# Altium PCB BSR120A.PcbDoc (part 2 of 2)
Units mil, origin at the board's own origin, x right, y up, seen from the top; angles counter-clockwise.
Board outline 3250 x 2500 mil, 4 copper layers (Top Layer, MidLayer1, MidLayer2, Bottom Layer), stack 61.2 mil thick; 56 components, 15 nets, 102 pads, 73 vias.
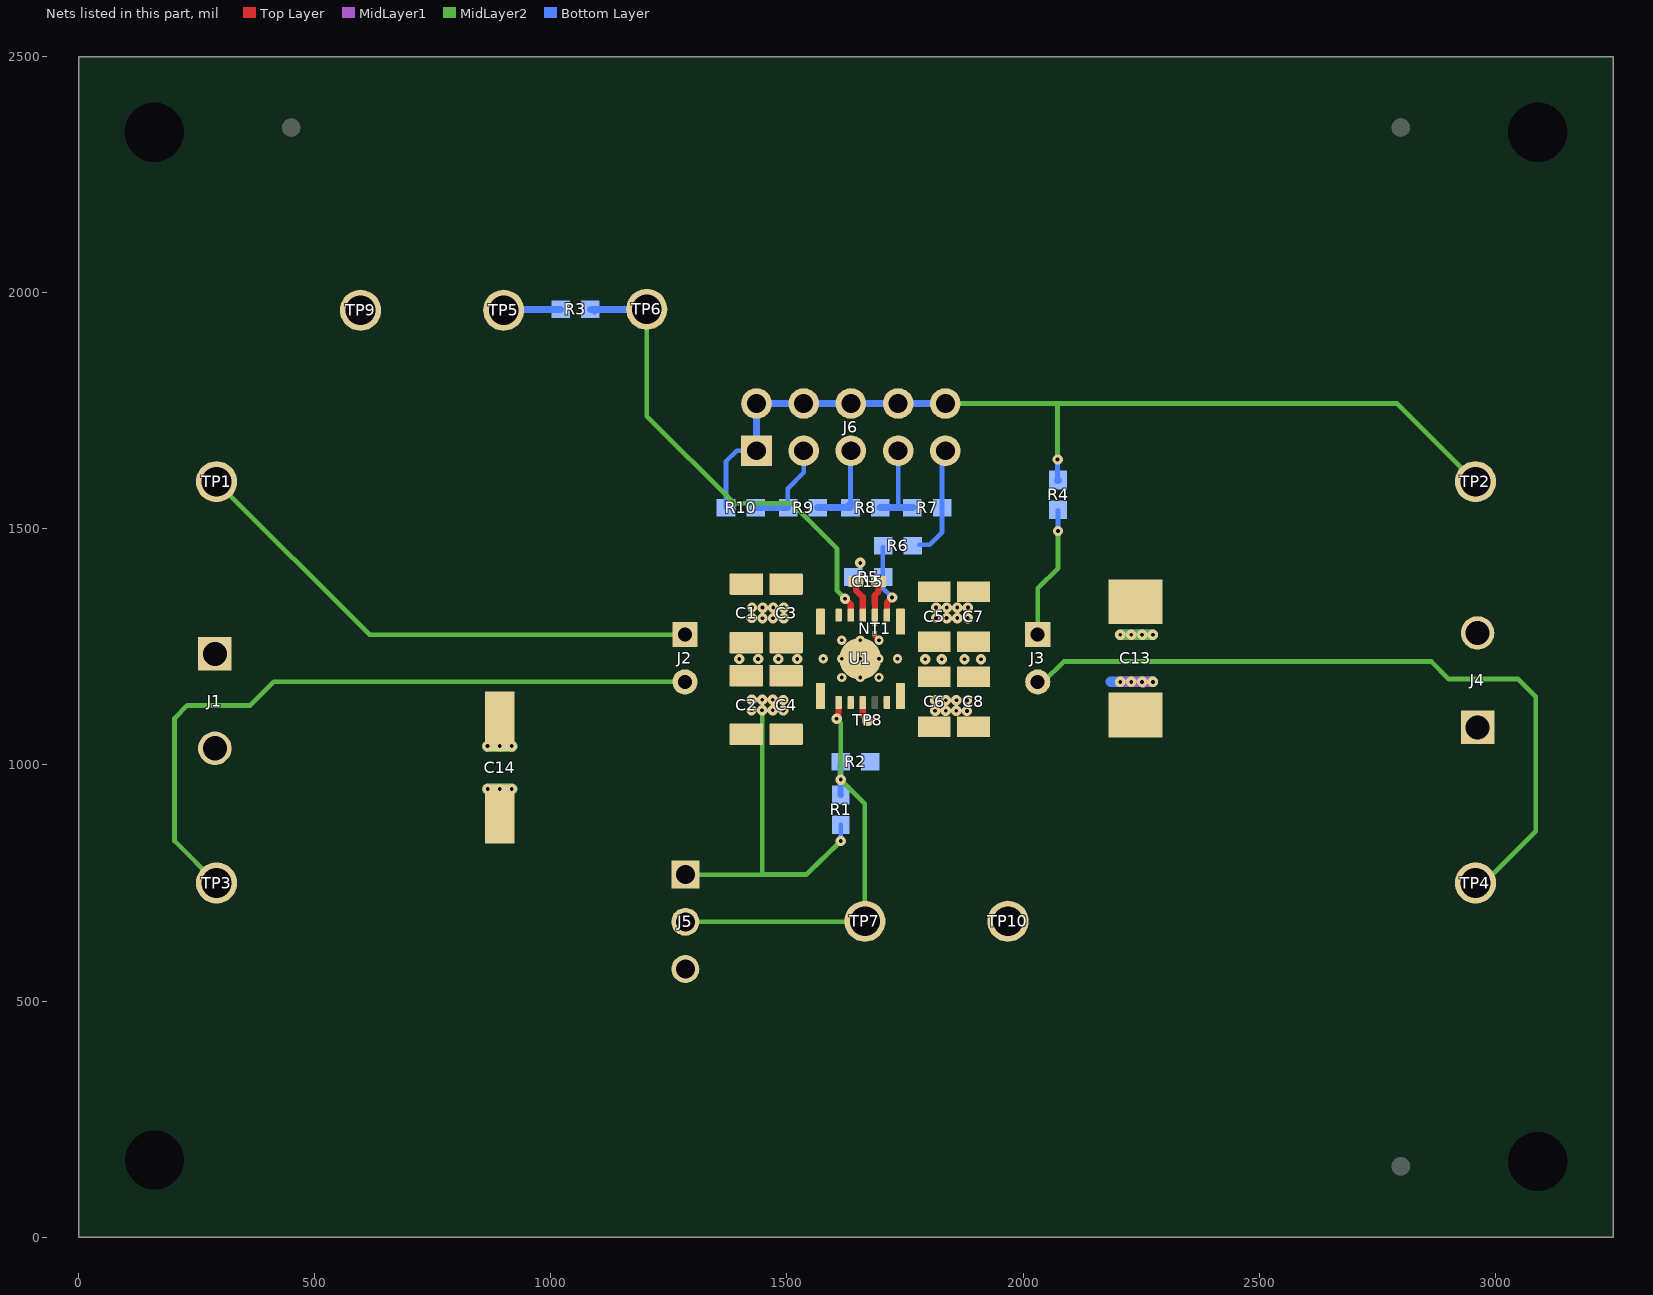
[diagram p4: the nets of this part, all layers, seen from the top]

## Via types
v1: diameter 22, hole 8, Top Layer to Bottom Layer, 62 vias
v2: diameter 19.68, hole 7.87, Top Layer to Bottom Layer, 11 vias

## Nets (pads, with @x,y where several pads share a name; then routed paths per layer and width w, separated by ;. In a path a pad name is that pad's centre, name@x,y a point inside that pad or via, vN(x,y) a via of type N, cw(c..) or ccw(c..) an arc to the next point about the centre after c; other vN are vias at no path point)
2.5: J6.9 R6.2 R7.1 | length 234.8
  Bottom Layer w10: R6.2@1780.25,1466.25 1801.88,1466.25 1828.5,1492.87 R7.1@1828.5,1545 1828.5,1658.6 J6.9@1835.4,1665.5
3.3: J6.7 R7.2 R8.1 | length 188.9
  Bottom Layer w10: 1735.4,1545.6 J6.7@1735.4,1665.5
  Bottom Layer w15: R8.1@1697.5,1545 R7.2@1766.5,1545
5.0: J6.5 R8.2 R9.1 | length 213.9
  Bottom Layer w10: R8.2@1634.5,1545 J6.5@1634.5,1664.6
  Bottom Layer w15: R9.1@1564.5,1545 R8.2@1634.5,1545 ; J6.5@1634.5,1664.6 J6.5@1635.4,1665.5 ; R8.2@1635.4,1554.9 R8.2@1634.5,1554.01 ; R8.2@1634.5,1545 R8.2@1634.5,1554.01 ; R8.2@1634.5,1545 1630,1549.5 R8.2@1634.5,1554.01
12: J6.3 R9.2 R10.1 | length 202.3
  Bottom Layer w10: R9.2@1501.5,1545 1501.5,1585.5 1535.4,1619.4 J6.3@1535.4,1665.5
  Bottom Layer w15: R10.1@1433.7,1545 R9.2@1501.5,1545
15: J6.1 J6.2 J6.4 J6.6 J6.8 J6.10 R4.2 R10.2 TP2.1 | length 2047.6
  MidLayer2 w10: J6.10@1835.4,1765.5 2792.5,1765.5 2958.74,1599.26 TP2.1@2975.26,1599.26 ; v1(2073.1,1646.9) 2073.1,1765.4 ; TP2.1@2957.26,1599.26 TP2.1@2958,1600
  Bottom Layer w10: R10.2@1370.7,1545 1370.7,1642.7 1393.5,1665.5 J6.1@1435.4,1665.5 ; R4.2@2073.1,1602.6 v1(2073.1,1646.9)
  Bottom Layer w15: J6.1@1435.4,1665.5 J6.2@1435.4,1765.5 J6.4@1535.4,1765.5 J6.6@1635.4,1765.5 J6.8@1735.4,1765.5 J6.10@1835.4,1765.5 ; R4.2@2074,1603.5 2073.1,1602.6 R4.2@2075,1602.6
AGND: C15.2 NT1.1 R5.1 U1.10 | length 74.3
  Top Layer w13: U1.10@1686.16,1317.26 1686.02,1359.02 1693.54,1366.54 C15.2@1693.54,1388.48
  other v1: 1655,1428
EN: J5.2 R1.1 R2.2 TP7.1 U1.2 | length 933.5
  Top Layer w13: v1@1609.39,1101.02 U1.2@1609.39,1132.22
  MidLayer2 w10: J5.2@1284.74,667.8 1663.8,667.8 TP7.1@1665,669 1665,918 v1(1614,969) 1614,1089 v1(1605,1098)
  Bottom Layer w13: R2.2@1613.5,1004 1613.5,936.99 R1.1@1614,936.5
FB: R5.2 R6.1 U1.9 | length 157.3
  Top Layer w13: U1.9@1711.75,1317.26 1711.75,1343.84 v1(1722.65,1354.74)
  Bottom Layer w10: R6.1@1703.5,1461 1703.1,1461.41 1703.1,1374.29 v1(1722.65,1354.74)
NetC15_1: C15.1 U1.11 | length 76.8
  Top Layer w13: C15.1@1646,1388 1646,1370 1660.57,1355.43 U1.11@1660.57,1317.26
NetTP8_1: TP8.1 U1.4 | length 41.5
  Top Layer w13: U1.4@1660.57,1132.22 1660.57,1105.43 TP8.1@1671,1095
PG_PU: R3.1 TP5.1 | length 119.5
  Bottom Layer w15: TP5.1@901,1965 R3.1@1020.5,1965
PGND: C1.1 C2.1 C3.1 C4.1 C5.1 C6.1 C7.1 C8.1 C13.2 C14.2 J1.2 J2.2 J3.2 J4.1 J5.3 NT1.2 R2.1 TP3.1 TP4.1 TP9.1 TP10.1 U1.3 U1.6 U1.13 U1.15 | length 3384.7
  Top Layer w10: 1686,1272.93 NT1.2@1686,1279
  MidLayer1 w22: v1(2206,1176) v1(2275,1176) ; v1@2252.6,1176 2253.08,1175.52 v1@2253.56,1176
  MidLayer2 w10: TP3.1@292,750 203,839 203,1099 230,1126 363,1126 413,1176 J2.2@1284,1176 ; J3.2@2018,1163 J3.2@2024,1169 ; J3.2@2018,1175 J3.2@2024,1169 ; J3.2@2043.82,1162 2031,1162 J3.2@2024,1169 ; TP4.1@2934,750 TP4.1@2958,750 ; TP4.1@2976,750 3086,860 3086,1145 3049,1182 2902,1182 2865,1219 2086,1219 2043,1176 J3.2@2031,1176 J3.2@2024,1169
  MidLayer2 w24: v1(866.18,949.18) v1(917.18,949.2)
  Bottom Layer w22: 2185.56,1176 v1(2229,1176) 2252.6,1176 2253.08,1175.52 2253.56,1176 v1(2275,1176)
  Bottom Layer w24: v1(866.18,949.18) v1(917.18,949.2)
  other v1: 891.68,949.19 2252,1176 1398.92,1224.48 1438.92,1224.48 1481.92,1224.48 1521.92,1224.48 1793,1224 1828,1224 1876,1224 1911,1224
  other v2: 1616.08,1185.37 1655.45,1185.37 1694.82,1185.37 1576.71,1224.74 1616.08,1224.74 1655.45,1224.74 1694.82,1224.74 1734.19,1224.74 1616.08,1264.11 1655.45,1264.11 1694.82,1264.11
PGOOD: R3.2 TP6.1 U1.12 | length 1021.9
  Top Layer w13: v1(1623,1352) 1634.98,1340.02 U1.12@1634.98,1317.26
  MidLayer2 w10: TP6.1@1203,1965 1203,1739 1388,1554 1510,1554 1606,1458 1606,1369 v1(1623,1352)
  Bottom Layer w15: R3.2@1083.5,1965 R3.2@1095,1965 ; R3.2@1092,1962 R3.2@1095,1965 ; TP6.1@1203,1965 R3.2@1095,1965
VIN: C1.2 C2.2 C3.2 C4.2 C14.1 J1.1 J2.1 J5.1 R1.2 TP1.1 U1.1 U1.14 | length 1967.9
  MidLayer2 w10: TP1.1@292.74,1599.26 616,1276 J2.1@1284,1276 ; J5.1@1284.74,767.8 1447,767.93 ; v1(1447.35,1115.7) 1447.35,768.27 1447,767.93 ; v1@1492.56,1135.83 v1@1492.73,1136 ; v1(1614,839) 1541,768 1447,767.93
  MidLayer2 w24: v1(866.02,1040) v1(917.02,1040.02)
  Bottom Layer w10: v1(1614,839) R1.2@1614,873.5
  Bottom Layer w24: v1(866.02,1040) v1(917.02,1040.02)
  other v1: 891.52,1040.01 1492.21,1115.4 1424.91,1115.7 1469.78,1115.7 1425.13,1138 1447.57,1138 1470,1138 1492.43,1137.7 1425.65,1311.25 1448.08,1310.95 1470.51,1310.95 1492.94,1310.95 1448.3,1333.25 1470.73,1333.25 1493.17,1333.25 1425.87,1333.55
VOUT: C5.2 C6.2 C7.2 C8.2 C13.1 J3.1 J4.2 R4.1 U1.7 U1.8 | length 419.3
  MidLayer2 w10: J3.1@2031,1276 2031,1374 2074,1417 v1(2074,1495.5)
  MidLayer2 w22: v1(2206,1276) v1(2275,1276)
  Bottom Layer w10: v1(2074,1495.5) R4.1@2074,1539.5
  Bottom Layer w22: v1(2206,1276) v1(2275,1276)
  other v1: 1881.08,1114.4 1813.78,1114.7 1836.21,1114.7 1858.64,1114.7 1814,1137 1836.43,1137 1858.87,1137 1881.3,1136.7 2229,1276 2252,1276 1815.57,1311.3 1838,1311 1860.43,1311 1882.87,1311 1838.22,1333.3 1860.65,1333.3 1883.09,1333.3 1815.79,1333.6
pads on no net: FID1.1 FID2.1 FID3.1 FID4.1 FID5.1 FID6.1 SH-J5.0 SH-J6.0 U1.5

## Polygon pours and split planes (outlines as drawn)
PGND on Top Layer "PGND" (solid, pour order 348): 3251.65,2496.39 3251.67,-3.61 1.65,-3.61 1.65,2496.39
VIN on Top Layer "VIN_L01_P342" (solid, remove dead copper, pour order 342): 1372,1407 1372,1295 1541,1295 1561,1275 1581,1275 1582,1276 1582,1330 1536,1376 1536,1407
VIN on Top Layer "VIN_L01_P341" (solid, remove dead copper, pour order 341): 1372,1150 1537,1150 1561,1174 1581,1174 1581,1087 1534,1040 1372,1040
VOUT on Top Layer "VOUT_L01_P340" (solid, remove dead copper, pour order 340): 1948.2,1391 1948.2,1296 1771,1296 1751,1276 1731,1276 1730,1277 1730,1341 1780,1391
VOUT on Top Layer "VOUT_L01_P338" (solid, remove dead copper, pour order 338): 1938,1149 1775,1149 1750,1174 1730,1174 1730,1089.08 1763.08,1056 1938,1056
AGND on Top Layer "AGND_L01_P343" (solid, remove dead copper, pour order 343): 1643,1438 1643,1302.29 1709.18,1302.29 1709.95,1301.52 1711.57,1303.13 1711.56,1434.91 1700.94,1445.53 ccw(c1678.11,-22492.67) 1650.52,1445.53
VIN on MidLayer1 "Top-Vin" (solid, remove dead copper, pour order 350): 738.6,1015 1534,1015 1534,1152 1362,1152 1362,1298 1534,1298 1534,1468 212,1468 212,1136 617.6,1136
VOUT on MidLayer1 "Top-Vout" (solid, remove dead copper, pour order 352): 2527.44,1014 1785,1014 1785,1153 1946,1153 1946,1298 1785,1298 1785,1471.5 3046,1471.5 3046,1193.48 2706.92,1193.48
PGND on MidLayer1 "Layer_2-PGND" (solid, remove dead copper, pour order 354): 0,-0.01 3250,0 3250,2500 0,2500
PGND on Bottom Layer "Layer_2-PGND" (solid, remove dead copper, pour order 362): 0,-0.01 3250,0 3250,2500 0,2500
PGND on MidLayer2 "PGND" (solid, pour order 360): 3250,0 0,0.15 0,2500 3250,2500

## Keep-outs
Keep-Out Layer:
  lines w10: 0,-6 0,2496 3250,2496 3250,-6 0,-6
  text ".Layer_Name" at 72.5,-1858.99 h60

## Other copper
Top Layer:
  region net VOUT: 2306.06,1395.48 2172.92,1395.48 2172.92,1261.34 2306.06,1261.34
  rectangle net VIN: 855,1028 929,1158
  region net PGND: 928.2,961.2 854.2,961.2 854.2,831.2 928.2,831.2
  rectangle net PGND: 2169.94,1056.52 2303.08,1190.66
  pour cut-out: 158.66,322.51 166.66,322.51 cw(c166.66,167.51) 321.66,167.51 321.66,158.51 cw(c165.66,158.51) 165.66,2.51 156.66,2.51 cw(c156.66,157.51) 1.66,157.51 1.66,165.51 cw(c158.66,165.51)
  pour cut-out: 2930.49,157.66 2930.49,165.66 cw(c3085.49,165.66) 3085.49,320.66 3094.49,320.66 cw(c3094.49,164.66) 3250.49,164.66 3250.49,155.66 cw(c3095.49,155.66) 3095.49,0.66 3087.49,0.66 cw(c3087.49,157.66)
  pour cut-out: 3092.34,2180.49 3084.34,2180.49 cw(c3084.34,2335.49) 2929.34,2335.49 2929.34,2344.49 cw(c3085.34,2344.49) 3085.34,2500.49 3094.34,2500.49 cw(c3094.34,2345.49) 3249.34,2345.49 3249.34,2337.49 cw(c3092.34,2337.49)
  pour cut-out: 319.51,2342.34 319.51,2334.34 cw(c164.51,2334.34) 164.51,2179.34 155.51,2179.34 cw(c155.51,2335.34) -0.49,2335.34 -0.49,2344.34 cw(c154.51,2344.34) 154.51,2499.34 162.51,2499.34 cw(c162.51,2342.34)
  pour cut-out: 1631.92,1401 1662,1401 1662,1375.48 1631.92,1375.48
  text ".Layer_Name" at -6.24,-1858.99 h60
MidLayer1:
  pour cut-out: 61,166 61,161 ccw(c159,161) 159,63 164,63 ccw(c164,160) 261,160 261,166 ccw(c164,166) 164,263 158,263 ccw(c158,166)
  pour cut-out: 61,166 61,161 ccw(c159,161) 159,63 164,63 ccw(c164,160) 261,160 261,166 ccw(c164,166) 164,263 158,263 ccw(c158,166)
  pour cut-out: 3087,60 3092,60 ccw(c3092,158) 3190,158 3190,163 ccw(c3093,163) 3093,260 3087,260 ccw(c3087,163) 2990,163 2990,157 ccw(c3087,157)
  pour cut-out: 3087,60 3092,60 ccw(c3092,158) 3190,158 3190,163 ccw(c3093,163) 3093,260 3087,260 ccw(c3087,163) 2990,163 2990,157 ccw(c3087,157)
  pour cut-out: 3190,2337 3190,2342 ccw(c3092,2342) 3092,2440 3087,2440 ccw(c3087,2343) 2990,2343 2990,2337 ccw(c3087,2337) 3087,2240 3093,2240 ccw(c3093,2337)
  pour cut-out: 3190,2337 3190,2342 ccw(c3092,2342) 3092,2440 3087,2440 ccw(c3087,2343) 2990,2343 2990,2337 ccw(c3087,2337) 3087,2240 3093,2240 ccw(c3093,2337)
  pour cut-out: 163,2440 158,2440 ccw(c158,2342) 60,2342 60,2337 ccw(c157,2337) 157,2240 163,2240 ccw(c163,2337) 260,2337 260,2343 ccw(c163,2343)
  pour cut-out: 163,2440 158,2440 ccw(c158,2342) 60,2342 60,2337 ccw(c157,2337) 157,2240 163,2240 ccw(c163,2337) 260,2337 260,2343 ccw(c163,2343)
  text ".Layer_Name" at -6.24,-1858.99 h60
MidLayer2:
  pour cut-out: 61,166 61,161 ccw(c159,161) 159,63 164,63 ccw(c164,160) 261,160 261,166 ccw(c164,166) 164,263 158,263 ccw(c158,166)
  pour cut-out: 3087,60 3092,60 ccw(c3092,158) 3190,158 3190,163 ccw(c3093,163) 3093,260 3087,260 ccw(c3087,163) 2990,163 2990,157 ccw(c3087,157)
  pour cut-out: 3190,2337 3190,2342 ccw(c3092,2342) 3092,2440 3087,2440 ccw(c3087,2343) 2990,2343 2990,2337 ccw(c3087,2337) 3087,2240 3093,2240 ccw(c3093,2337)
  pour cut-out: 163,2440 158,2440 ccw(c158,2342) 60,2342 60,2337 ccw(c157,2337) 157,2240 163,2240 ccw(c163,2337) 260,2337 260,2343 ccw(c163,2343)
  pour cut-out: 1284,1136.78 cw(c1284,1176) 1244.78,1176 cw(c1284,1176) 1284,1215.22 cw(c1284,1176) 1323.22,1176 cw(c1284,1176)
  pour cut-out: 2031,1136.78 cw(c2031,1176) 1991.78,1176 cw(c2031,1176) 2031,1215.22 cw(c2031,1176) 2070.22,1176 cw(c2031,1176)
  text ".Layer_Name" at -6.24,-1858.99 h60
Bottom Layer:
  rectangle net AGND: 1620,1373 1666,1439
  pour cut-out: 158.66,322.51 166.66,322.51 cw(c166.66,167.51) 321.66,167.51 321.66,158.51 cw(c165.66,158.51) 165.66,2.51 156.66,2.51 cw(c156.66,157.51) 1.66,157.51 1.66,165.51 cw(c158.66,165.51)
  pour cut-out: 2930.49,157.66 2930.49,165.66 cw(c3085.49,165.66) 3085.49,320.66 3094.49,320.66 cw(c3094.49,164.66) 3250.49,164.66 3250.49,155.66 cw(c3095.49,155.66) 3095.49,0.66 3087.49,0.66 cw(c3087.49,157.66)
  pour cut-out: 3092.34,2180.49 3084.34,2180.49 cw(c3084.34,2335.49) 2929.34,2335.49 2929.34,2344.49 cw(c3085.34,2344.49) 3085.34,2500.49 3094.34,2500.49 cw(c3094.34,2345.49) 3249.34,2345.49 3249.34,2337.49 cw(c3092.34,2337.49)
  pour cut-out: 319.51,2342.34 319.51,2334.34 cw(c164.51,2334.34) 164.51,2179.34 155.51,2179.34 cw(c155.51,2335.34) -0.49,2335.34 -0.49,2344.34 cw(c154.51,2344.34) 154.51,2499.34 162.51,2499.34 cw(c162.51,2342.34)
  text ".Layer_Name" at 72.5,-1858.99 h60

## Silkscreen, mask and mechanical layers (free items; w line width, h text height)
Top Overlay:
  circle w10: c1570.92,1096.48 r10
  circle w10: c1569.51,1096.48 r1.41
  lines w6: 1346.25,526.12 1355.25,526.12 1404.25,526.12 1404.25,545 ; 1346.25,807.12 1355.25,807.12 1404.25,807.12 1404.25,791 ; 1348.25,670.12 1404.25,670.12 1405.25,669.12 ; 1405.25,653 1405.25,669.12 ; 1405.25,690 1405.25,669.12
  text "'.PRJ_Title'" at 1169,2279 h120
  text "PG_PU" at 792,2067 h50
  text "PGOOD" at 1094,2067 h50
  text "PGND" at 505,2066 h50
  text "3.3V" at 1759,1841 h50 r90
  text "2.5V" at 1859,1841 h50 r90
  text "15V" at 1459,1840 h50 r90
  text "12V" at 1558,1838 h50 r90
  text "5.0V" at 1658,1836 h50 r90
  text "VIN" at 242,1767 h50
  text "VOUT" at 2874,1763 h50
  text "S+" at 250,1696 h50
  text "S+" at 2919.75,1695.26 h50
  text "VOUT  / SELECT" at 1936,1656 h50
  text "VOUT" at 3007.5,1426 h50
  text "VIN" at 67,1424 h50
  text "+" at 2210,1416 h70
  text "+" at 378,1406 h70
  text "Vout" at 1863,1345 h50
  text "Vin" at 1207,1327 h50
  text "+" at 2098,1298 h45
  text "+" at 1172,1280.01 h45
  text "+" at 756,1144 h50
  text "PGND" at 50,848 h50
  text "PGND" at 3002,848 h50
  text "ON" at 1364,716 h50
  text "VIN" at 242,606 h50
  text "VOUT" at 2874.25,603.74 h50
  text "OFF" at 1357.25,571.12 h50
  text "S-" at 254,538 h50
  text "S-" at 2920,536 h50
  text "EN" at 1629,524 h50
  text "PGND" at 1876,524 h50
  text "ENABLE" at 1170,429 h50
  text "'.PRJ_Number'.PCB_Rev" at 2403,63 h45
  text ".Layer_Name" at 72.5,-1858.99 h60
Bottom Overlay:
  text ".Layer_Name" at 72.5,-1858.99 h60
Top Paste:
  text ".Layer_Name" at 72.5,-1858.99 h60
Bottom Paste:
  text ".Layer_Name" at 72.5,-1858.99 h60
Top Solder:
  text ".Layer_Name" at 72.5,-1858.99 h60
  text ".Layer_Name" at 72.5,-1858.99 h60
Bottom Solder:
  text ".Layer_Name" at 72.5,-1858.99 h60
Drill Guide:
  text ".Layer_Name" at 72.5,-1858.99 h60
M1 Board Outline:
  the board outline again, w4
  text ".Layer_Name" at -6.24,-1858.99 h60
M2 Board Dimensions:
  rectangle: -379.5,-1400.5 -4.5,-1275.5
  rectangle: -504.5,-1275.5 -379.5,-1150.5
  lines w7: -504.5,-1275.5 495.5,-1275.5 ; -379.5,-1400.5 -379.5,-1150.5 ; -254.5,-1400.5 -254.5,-1150.5 ; -4.5,-1400.5 -4.5,-1150.5 ; 245.5,-1400.5 245.5,-1150.5 ; -504.5,-1400.5 -504.5,-1150.5 495.5,-1150.5 495.5,-1400.5 -504.5,-1400.5
  text ".Layer_Name" at -6.24,-1858.99 h60
M3 3D STEP Top:
  text ".Layer_Name" at -6.24,-1858.99 h60
M4 3D STEP Bottom:
  text ".Layer_Name" at -6.24,-1858.99 h60
M5 Assembly Top:
  lines w10: -816.18,-1930.67 5033.85,-1930.67 ; -816.18,-1727.33 5033.85,-1727.33 ; -816.18,-1524 -816.18,-2134 3188.81,-2134 ; 759.82,-2134 -815.68,-2134 -815.68,-1524 5033.85,-1524 5033.85,-2134 2712.44,-2134 ; 1467.71,-2134 1467.71,-1524 ; 2498.49,-1727.33 2498.49,-1524 ; 3220.38,-1727.33 3220.38,-1524 ; 3724.27,-2140.5 3724.27,-1937.67
  text "COMPONENTS MARKED 'DNP' SHOULD NOT BE POPULATED." at 526.95,-1319 h60
  text "ASSEMBLY VARIANT:" at 526.45,-1434.5 h60
  text ".VariantName" at 1554.58,-1434.5 h60
  text "PCB VIEWED FROM TOP SIDE" at -772.37,-1656.17 h60
  text "BOARD #:" at 1511.22,-1656.17 h60
  text ".PRJ_Number" at 1970.1,-1656.17 h60
  text "REV:" at 2657.12,-1656.17 h60
  text ".PCB_Rev" at 2889.57,-1656.17 h60
  text "SVN REV:" at 3290.4,-1656.17 h60
  text ".VersionControl_RevNumber" at 3784.59,-1656.17 h60
  text "TID #:" at 1511.22,-1859.5 h60
  text ".TID" at 1970.1,-1859.5 h60
  text "PLOT NAME =" at -772.37,-2064.84 h60
  text ".plot_File_Name" at -6.24,-2064.84 h60
  text "GENERATED    :" at 1513.22,-2064.84 h60
  text ".Print_Date" at 2237.05,-2064.84 h60
  text ".Print_Time" at 2828.25,-2064.84 h60
  text "TEXAS INSTRUMENTS" at 3895.9,-2064.84 h60
M6 Assembly Bottom:
  lines w10: -816.68,-1727.83 5033.85,-1727.83 ; -814.68,-1931.17 5033.85,-1931.17 ; 508.64,-2141 508.64,-1938.17 ; 1051.9,-1727.83 1051.9,-1524.5 ; 1540.16,-2134.5 5033.85,-2134.5 3575.46,-2134.5 ; 1780.32,-2134.5 -816.68,-2134.5 -816.68,-1524.5 5033.85,-1524.5 ; 1793.47,-1727.83 1793.47,-1524.5 ; 2824.25,-2134.5 2824.25,-1524.5 ; 5032.85,-2134.5 5032.85,-1524.5 ; 5033.35,-2134.5 5033.35,-1524.5
  text "COMPONENTS MARKED 'DNP' SHOULD NOT BE POPULATED." at 5199.86,-1318.5 h60
  text ".VariantName" at 3860.59,-1434.5 h60
  text "ASSEMBLY VARIANT:" at 4860.22,-1434.5 h60
  text ".VersionControl_RevNumber" at 531,-1656.67 h60
  text "SVN REV:" at 1017.32,-1656.67 h60
  text ".PCB_Rev" at 1422.08,-1656.67 h60
  text "REV:" at 1662.4,-1656.67 h60
  text "BOARD #:" at 2729.57,-1656.67 h60
  text "PCB VIEWED FROM BOTTOM SIDE" at 4989.53,-1656.67 h60
  text ".PRJ_Number" at 2311,-1661 h60
  text ".TID" at 2282.49,-1860 h60
  text "TID #:" at 2729.57,-1860 h60
  text "TEXAS INSTRUMENTS" at 340.95,-2065.34 h60
  text ".Print_Time" at 1522.77,-2065.34 h60
  text ".Print_Date" at 2141.53,-2065.34 h60
  text "GENERATED    :" at 2924.42,-2065.34 h60
  text ".plot_File_Name" at 4321.83,-2065.34 h60
  text "PLOT NAME =" at 4989.53,-2065.34 h60
M9 Title Sheet:
  drawing of 52 lines, arcs and shapes, not listed
  text "1" at 411,4431 h70
  text "2" at 3271,4431 h70
  text "3" at 6151,4431 h70
  text "4" at 9021,4431 h70
  text "A" at -941,3525 h70
  text "A" at 10359,3525 h70
  text "B" at -941,1633 h70
  text "B" at 10359,1633 h70
  text "C" at -941,-277 h70
  text "C" at 10359,-277 h70
  text "PROJECT TITLE:" at 7319,-1423 h45
  text ".PRJ_Title" at 7369,-1556.33 h60
  text "DESIGNED FOR:" at 7319,-1724 h45
  text ".PRJ_Customer" at 7369,-1864 h70
  text "FILE NAME:" at 7319,-2024 h45
  text ".PCB_File_Name_No_Path" at 7369,-2144 h70
  text "D" at -941,-2167 h70
  text "D" at 10359,-2167 h70
  text "Texas Instruments (TI) and/or its licensors do not warrant the accuracy or completeness of this specification" at 710.5,-2313.84 h60
  text "ENGINEER:" at 7319,-2314 h45
  text "LAYOUT BY:" at 8824,-2314 h45
  text "or any information contained therein. TI and/or its licensors do not warrant that this design will meet" at 665.51,-2426.5 h60
  text ".PRJ_Engineer" at 7369,-2468.99 h70
  text ".PCB_Layout" at 8874.5,-2468.99 h70
  text "the specifications, will be suitable for your application or fit for any particular purpose, or will operate in" at 665.51,-2539.17 h60
  text "ALTIUM DESIGNER VERSION:" at 8824,-2624 h45
  text "an implementation. TI and/or its licensors do not warrant that the design is production worthy. You should" at 665.51,-2651.83 h60
  text ".print_Scale" at 7369,-2757.33 h70
  text ".Application_BuildNumber" at 8874.5,-2757.33 h70
  text "completely validate and test your design implementation to confirm the system functionality for your application." at 710.5,-2764.5 h60
  text "1" at 411,-2969 h70
  text "2" at 3271,-2969 h70
  text "3" at 6151,-2969 h70
  text "4" at 9021,-2969 h70
M10 Fab Notes:
  drawing of 192 lines, arcs and shapes, not listed
  text "DESIGN INFORMATION" at 8358.52,4155.17 h60
  text "MIN. TRACK WIDTH:" at 7713.96,4023.05 h60
  text "mil" at 8965.46,4023.05 h60
  text "10" at 8744,4018.24 h60
  text "MIN. CLEARANCE:" at 7713.96,3898.92 h60
  text "mil" at 8965.46,3898.92 h60
  text "8" at 8744,3895.11 h60
  text "MIN. VIA PAD SIZE:" at 7713.96,3774.8 h60
  text "mil" at 8965.46,3774.8 h60
  text "22" at 8744,3770 h60
  text "0.05mm (2MIL)" at 8408.96,3644.9 h60
  text "MINIMUM ANNULAR RING" at 7384.73,3636.67 h60
  text "EXTERNAL" at 9116.96,3636.67 h60
  text "PER" at 7584.73,3526.55 h60
  text "IPC-D-275 CLASS 2 LEVEL C" at 7804.73,3526.54 h60
  text "MIL, HOLES" at 9292.96,3426.07 h60
  text "+/-" at 8900.5,3417.48 h60
  text "+/-" at 9754.5,3417.48 h60
  text "REGISTRATION TOLERANCES:" at 7384.73,3416.42 h60
  text "METAL" at 8584.5,3416.42 h60
  text "5" at 9160.7,3416.42 h60
  text "3" at 9993.7,3416.42 h60
  text "MIL" at 10109.96,3416.42 h60
  text "HOLE SIZE TOLERANCE (UNLESS OTHERWISE SPECIFIED):" at 7384.73,3318.1 h60
  text "+/-" at 9754.5,3315.23 h60
  text "3" at 9993.7,3314.17 h60
  text "MIL" at 10109.96,3314.17 h60
  text "MATERIAL:" at 7309.96,3176.52 h60
  text "FR-4 High Tg" at 8296.4,3048 h60
  text "X" at 8151.96,3040.01 h60
  text "FR-408" at 7730.96,3035.49 h60
  text "OTHER" at 9218.96,3035.49 h60
  text "62 MIL (1.6mm) +/-10%" at 8051.06,2892.46 h60
  text "X" at 7930.96,2890.01 h60
  text "THICKNESS:" at 7384.73,2884.24 h60
  text "OTHER" at 9335.96,2884.24 h60
  text "TOLERANCE:" at 7384.73,2745.92 h60
  text "X" at 8232.96,2745.92 h60
  text "ANSI IPC-6012 TYPE 3 CLASS 2" at 8410.98,2745.92 h60
  text "OTHER +/-" at 8410.96,2601.73 h60
  text "BOW & TWIST:" at 7384.73,2456.54 h60
  text "X" at 8232.96,2456.54 h60
  text "ANSI IPC-6012 TYPE 3 CLASS 2" at 8410.98,2456.54 h60
  text "OTHER +/-" at 8410.96,2309.85 h60
  text "DRILLING:" at 7309.96,2179.23 h60
  text "NC_DRILL FILES" at 9070.96,2074.04 h60
  text "REFERENCE:" at 7384.73,2070.1 h60
  text "X" at 8041.96,2070.01 h60
  text "AS SHOWN" at 8219.96,2070.1 h60
  text "X" at 8942.96,2070.1 h60
  text "OTHER" at 9368.96,1927.85 h60
  text "PTH COPPER THICKNESS:" at 7384.41,1924.32 h60
  text "X" at 8523.64,1924.32 h60
  text "20-30 um" at 8651.64,1924.32 h60
  text "BOARD FINISH:" at 7309.96,1776.73 h60
  text "SILKSCREEN:" at 7465.18,1666.6 h60
  text "X" at 8422.96,1666.6 h60
  text "TOP" at 8539.96,1666.6 h60
  text "X" at 8932.96,1666.6 h60
  text "BOTTOM" at 9050.96,1666.6 h60
  text "SILKSCREEN COLOR:" at 7465.18,1511.41 h60
  text "X" at 8421.96,1511.41 h60
  text "WHITE" at 8539.96,1511.41 h60
  text "OTHER" at 9050.96,1511.41 h60
  text "X" at 8552.96,1367.96 h60
  text "GREEN" at 8670.96,1367.96 h60
  text "OTHER" at 9288.96,1367.96 h60
  text "SOLDER RESIST COLOR:" at 7465.18,1361.1 h60
  text "MATTE" at 8670.96,1213.71 h60
  text "SEMI-GLOSS" at 9288.5,1213.07 h60
  text "X" at 9147,1205 h60
  text "IMMERSION GOLD (ENIG)" at 8370.96,1040.94 h60
  text "ENEPIG" at 9708.5,1033.72 h60
  text "SURFACE FINISH:" at 7309.96,1032.72 h60
  text "X" at 8192.96,1032.72 h60
  text "IMM. TIN/SILVER OR EQUIV" at 7639.5,895.4 h60
  text "OTHER" at 9070.96,891.47 h60
  text "ARRAY/PANEL:" at 7309.96,736.09 h60
  text "CUT AND TRIM PER M1 BOARD OUTLINE" at 8370.96,727.87 h60
  text "N.C. ROUTE" at 8370.96,591.9 h60
  text "X" at 9058.96,591.9 h60
  text "V. SCORE" at 9236.96,591.9 h60
  text "CERTIFICATION:" at 7309.96,462.77 h60
  text "MATERIALS AND WORKMANSHIP FOR ALL PCBS" at 8034.96,462.77 h60
  text "TO MEET OR EXCEED THE REQUIREMENTS OF:" at 8034.96,368.71 h60
  text "X" at 7672.47,240.08 h60
  text "ANSI IPC-A-600F CLASS ->" at 7800.46,240.08 h60
  text "X" at 9448.47,240.08 h60
  text "2" at 9558.46,240.08 h60
  text "1" at 9243.46,238.58 h60
  text "3" at 9912.46,238.58 h60
  text "X" at 8484.47,92.39 h60
  text "RoHS" at 8612.46,92.39 h60
  text "OTHER" at 9256.86,92.39 h60
  text "PER ORDER" at 9653.92,92.39 h60
  text "ALL BOARDS MUST MEET OR EXCEED UL94-V0 REQUIREMENTS." at 7337.5,-61.43 h60
  text "PCB MUST BEAR THE UL94V-0 UL REGISTERED MATERIAL ID NUMBER" at 7337.5,-177.5 h60
  text "ADDITIONAL REQUIREMENTS:" at 7309.96,-346.92 h60
  text "MICROSECTION:" at 7384.73,-454.05 h60
  text "YES" at 8290.46,-454.05 h60
  text "REQUIRED" at 9151.96,-598.38 h60
  text "BARE BOARD ELEC. TEST:" at 7384.73,-601.24 h60
  text "NONE" at 8690.46,-601.24 h60
  text "X" at 9033.96,-601.24 h60
  text "PER ORDER" at 9743.96,-601.24 h60
  text "X" at 7378.96,-753.24 h60
  text "7.87 MIL VIAS REQUIRE NON-CONDUCTIVE FILL AND PLANARIZE" at 7440,-807 h59
  text "XX MIL VIAS REQUIRE CONDUCTIVE FILL AND PLANARIZE" at 7501.88,-910.16 h60
  text "OUTER XX MIL TRACES REQUIRE 50 OHM SINGLE-ENDED IMPEDANCE" at 7500.89,-1073.54 h58
  text "LAYER 2 & 3 (INNER LAYERS) XX MIL WIDE, XX MIL SPACE / TRACES REQUIRE 100 OHM DIFFERENTIAL IMPEDANCE" at 7492.89,-1309.26 h60
  text ".Layer_Name" at -6.24,-1858.99 h60
M11 Gerber Information:
  lines w10: -816.18,-1930.67 5033.85,-1930.67 ; -816.18,-1727.33 5033.85,-1727.33 ; -816.18,-1524 -816.18,-2134 3188.81,-2134 ; 759.82,-2134 -815.68,-2134 -815.68,-1524 5033.85,-1524 5033.85,-2134 2712.44,-2134 ; 1467.71,-2134 1467.71,-1524 ; 2498.49,-1727.33 2498.49,-1524 ; 3220.38,-1727.33 3220.38,-1524 ; 3724.27,-2140.5 3724.27,-1937.67
  text "ALL ARTWORK VIEWED FROM TOP SIDE" at -772.37,-1656.17 h60
  text "BOARD #:" at 1511.22,-1656.17 h60
  text ".PRJ_Number" at 1970.1,-1656.17 h60
  text "REV:" at 2657.12,-1656.17 h60
  text ".PCB_Rev" at 2889.57,-1656.17 h60
  text "SVN REV:" at 3290.4,-1656.17 h60
  text ".VersionControl_RevNumber" at 3784.59,-1656.17 h60
  text "LAYER NAME =" at -772.37,-1858.99 h60
  text "TID #:" at 1511.22,-1859.5 h60
  text ".TID" at 1970.1,-1859.5 h60
  text "PLOT NAME =" at -772.37,-2064.84 h60
  text ".plot_File_Name" at -6.24,-2064.84 h60
  text "GENERATED    :" at 1513.22,-2064.84 h60
  text ".Print_Date" at 2237.05,-2064.84 h60
  text ".Print_Time" at 2828.25,-2064.84 h60
  text "TEXAS INSTRUMENTS" at 3895.9,-2064.84 h60
M12 Stackup:
  drawing of 251 lines, arcs and shapes, not listed
  text "Layer" at 4163.48,4087 h50
  text "Name" at 4449.01,4087 h50
  text "Material" at 5081.62,4087 h50
  text "Thickness" at 5669.94,4087 h50
  text "Constant" at 6093.54,4087 h50
  text "Board Layer Stack" at 6499.53,4087 h50
  text "1" at 4163.48,3987 h50
  text "Top Overlay" at 4449.01,3987 h50
  text "2" at 4163.48,3887 h50
  text "Top Solder" at 4449.01,3887 h50
  text "Solder Resist" at 5081.62,3887 h50
  text "0.40mil" at 5669.94,3887 h50
  text "3.5" at 6093.54,3887 h50
  text "3" at 4163.48,3787 h50
  text "Top Layer" at 4449.01,3787 h50
  text "Copper" at 5081.62,3787 h50
  text "2.80mil" at 5669.94,3787 h50
  text "4" at 4163.48,3687 h50
  text "Dielectric1" at 4449.01,3687 h50
  text "FR-4 High Tg" at 5081.62,3687 h50
  text "5.00mil" at 5669.94,3687 h50
  text "4.2" at 6093.54,3687 h50
  text "5" at 4163.48,3587 h50
  text "MidLayer1" at 4449.01,3587 h50
  text "Copper" at 5081.62,3587 h50
  text "2.80mil" at 5669.94,3587 h50
  text "6" at 4163.48,3487 h50
  text "Dielectric2" at 4449.01,3487 h50
  text "FR-4 High Tg" at 5081.62,3487 h50
  text "40.00mil" at 5669.94,3487 h50
  text "4.2" at 6093.54,3487 h50
  text "7" at 4163.48,3387 h50
  text "MidLayer2" at 4449.01,3387 h50
  text "Copper" at 5081.62,3387 h50
  text "2.80mil" at 5669.94,3387 h50
  text "8" at 4163.48,3287 h50
  text "Dielectric3" at 4449.01,3287 h50
  text "FR-4 High Tg" at 5081.62,3287 h50
  text "5.00mil" at 5669.94,3287 h50
  text "4.2" at 6093.54,3287 h50
  text "9" at 4163.48,3187 h50
  text "Bottom Layer" at 4449.01,3187 h50
  text "Copper" at 5081.62,3187 h50
  text "2.80mil" at 5669.94,3187 h50
  text "10" at 4163.48,3087 h50
  text "Bottom Solder" at 4449.01,3087 h50
  text "Solder Resist" at 5081.62,3087 h50
  text "0.40mil" at 5669.94,3087 h50
  text "3.5" at 6093.54,3087 h50
  text "11" at 4163.48,2987 h50
  text "Bottom Overlay" at 4449.01,2987 h50
  text "(For Reference Only)" at 5093,2818 h75
  text ".Layer_Name" at -6.24,-1858.99 h60
M13 Component Bodies Top:
  text ".Layer_Name" at -6.24,-1858.99 h60
M14 Component Bodies Bottom:
  text ".Layer_Name" at -6.24,-1858.99 h60
M15 Courtyards Top:
  text ".Layer_Name" at -6.24,-1858.99 h60
M16 Courtyards Bottom:
  text ".Layer_Name" at -6.24,-1858.99 h60
Drill Drawing:
  circle w10: c3613.45,1973.28 r32.29
  lines w10: 3581.16,923.83 3645.74,923.83 3645.74,988.42 3581.16,988.42 3581.16,923.83 ; 3581.16,1069.14 3581.16,1085.29 3597.31,1101.43 3581.16,1117.58 3581.16,1133.72 3597.31,1133.72 3613.45,1117.58 3629.6,1133.72 3645.74,1133.72 3645.74,1117.58 3629.6,1101.43 3645.74,1085.29 3645.74,1069.14 3629.6,1069.14 3613.45,1085.29 3597.31,1069.14 3581.16,1069.14 ; 3581.16,1279.03 3645.74,1279.03 3613.45,1214.45 3581.16,1279.03 ; 3581.16,1359.76 3613.45,1375.9 3645.74,1359.76 3629.6,1392.05 3645.74,1424.34 3613.45,1408.2 3581.16,1424.34 3597.31,1392.05 3581.16,1359.76 ; 3581.16,1521.21 3597.31,1521.21 3613.45,1505.07 3629.6,1521.21 3645.74,1521.21 3629.6,1537.36 3645.74,1553.5 3629.6,1553.5 3613.45,1569.65 3597.31,1553.5 3581.16,1553.5 3597.31,1537.36 3581.16,1521.21 ; 3581.16,1682.67 3613.45,1650.38 3645.74,1682.67 3613.45,1714.96 3581.16,1682.67 ; 3581.16,1795.68 3645.74,1795.68 3645.74,1860.26 3581.16,1860.26 3581.16,1795.68 ; 3594.08,1808.6 3632.83,1808.6 3632.83,1847.35 3594.08,1847.35 3594.08,1808.6
  lines w12: 3523.14,880.24 7184.13,880.24 ; 3523.14,2042.71 7184.13,2042.71 ; 3917.71,734.93 3917.71,2188.02 ; 4267.1,734.93 4267.1,2188.02 ; 4955.33,734.93 4955.33,2188.02 ; 5257.93,734.93 5257.93,2188.02 ; 5695.91,734.93 5695.91,2188.02 ; 6427.69,734.93 6427.69,2188.02 ; 3523.14,734.93 7184.13,734.93 7184.13,2188.02 3523.14,2188.02 3523.14,734.93
  text "DRILL TABLE" at 5064,2411 h75
  text "Symbol" at 3610.33,2086.3 h84
  text "Count" at 3961.31,2086.3 h84
  text "Hole Size" at 4310.69,2086.3 h84
  text "Plated" at 4998.92,2086.3 h84
  text "Hole Type" at 5301.52,2086.3 h84
  text "Hole Tolerance (+)" at 5739.5,2086.3 h84
  text "Hole Tolerance (-)" at 6471.29,2086.3 h84
  text "11" at 3961.31,1940.99 h70
  text "7.87mil (0.200mm)" at 4310.69,1940.99 h70
  text "PTH" at 4998.92,1940.99 h70
  text "Round" at 5301.52,1940.99 h70
  text "28" at 3961.31,1795.68 h70
  text "8.00mil (0.203mm)" at 4310.69,1795.68 h70
  text "PTH" at 4998.92,1795.68 h70
  text "Round" at 5301.52,1795.68 h70
  text "3.00mil (0.076mm)" at 6471.29,1795.68 h70
  text "34" at 3961.31,1650.38 h70
  text "8.00mil (0.203mm)" at 4310.69,1650.38 h70
  text "PTH" at 4998.92,1650.38 h70
  text "Round" at 5301.52,1650.38 h70
  text "3.00mil (0.076mm)" at 5739.5,1650.38 h70
  text "3.00mil (0.076mm)" at 6471.29,1650.38 h70
  text "4" at 3961.31,1505.07 h70
  text "29.53mil (0.750mm)" at 4310.69,1505.07 h70
  text "PTH" at 4998.92,1505.07 h70
  text "Round" at 5301.52,1505.07 h70
  text "13" at 3961.31,1359.76 h70
  text "40.00mil (1.016mm)" at 4310.69,1359.76 h70
  text "PTH" at 4998.92,1359.76 h70
  text "Round" at 5301.52,1359.76 h70
  text "4" at 3961.31,1214.45 h70
  text "51.18mil (1.300mm)" at 4310.69,1214.45 h70
  text "PTH" at 4998.92,1214.45 h70
  text "Round" at 5301.52,1214.45 h70
  text "9" at 3961.31,1069.14 h70
  text "63.00mil (1.600mm)" at 4310.69,1069.14 h70
  text "PTH" at 4998.92,1069.14 h70
  text "Round" at 5301.52,1069.14 h70
  text "4" at 3961.31,923.83 h70
  text "125.00mil (3.175mm)" at 4310.69,923.83 h70
  text "NPTH" at 4998.92,923.83 h70
  text "Round" at 5301.52,923.83 h70
  text "107 Total" at 3961.31,778.53 h70
  text ".Layer_Name" at -6.24,-1858.99 h60
Mechanical 17:
  text ".Layer_Name" at -6.24,-1858.99 h60
Mechanical 18:
  text ".Layer_Name" at -6.24,-1858.99 h60
Mechanical 19:
  text ".Layer_Name" at -2.3,-1862.93 h60

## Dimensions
0,0 to 0,2500 on M2 Board Dimensions
0,0 to 3250,0 on M2 Board Dimensions
-504.5,-1400.5 to 495.5,-1400.5 on M2 Board Dimensions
